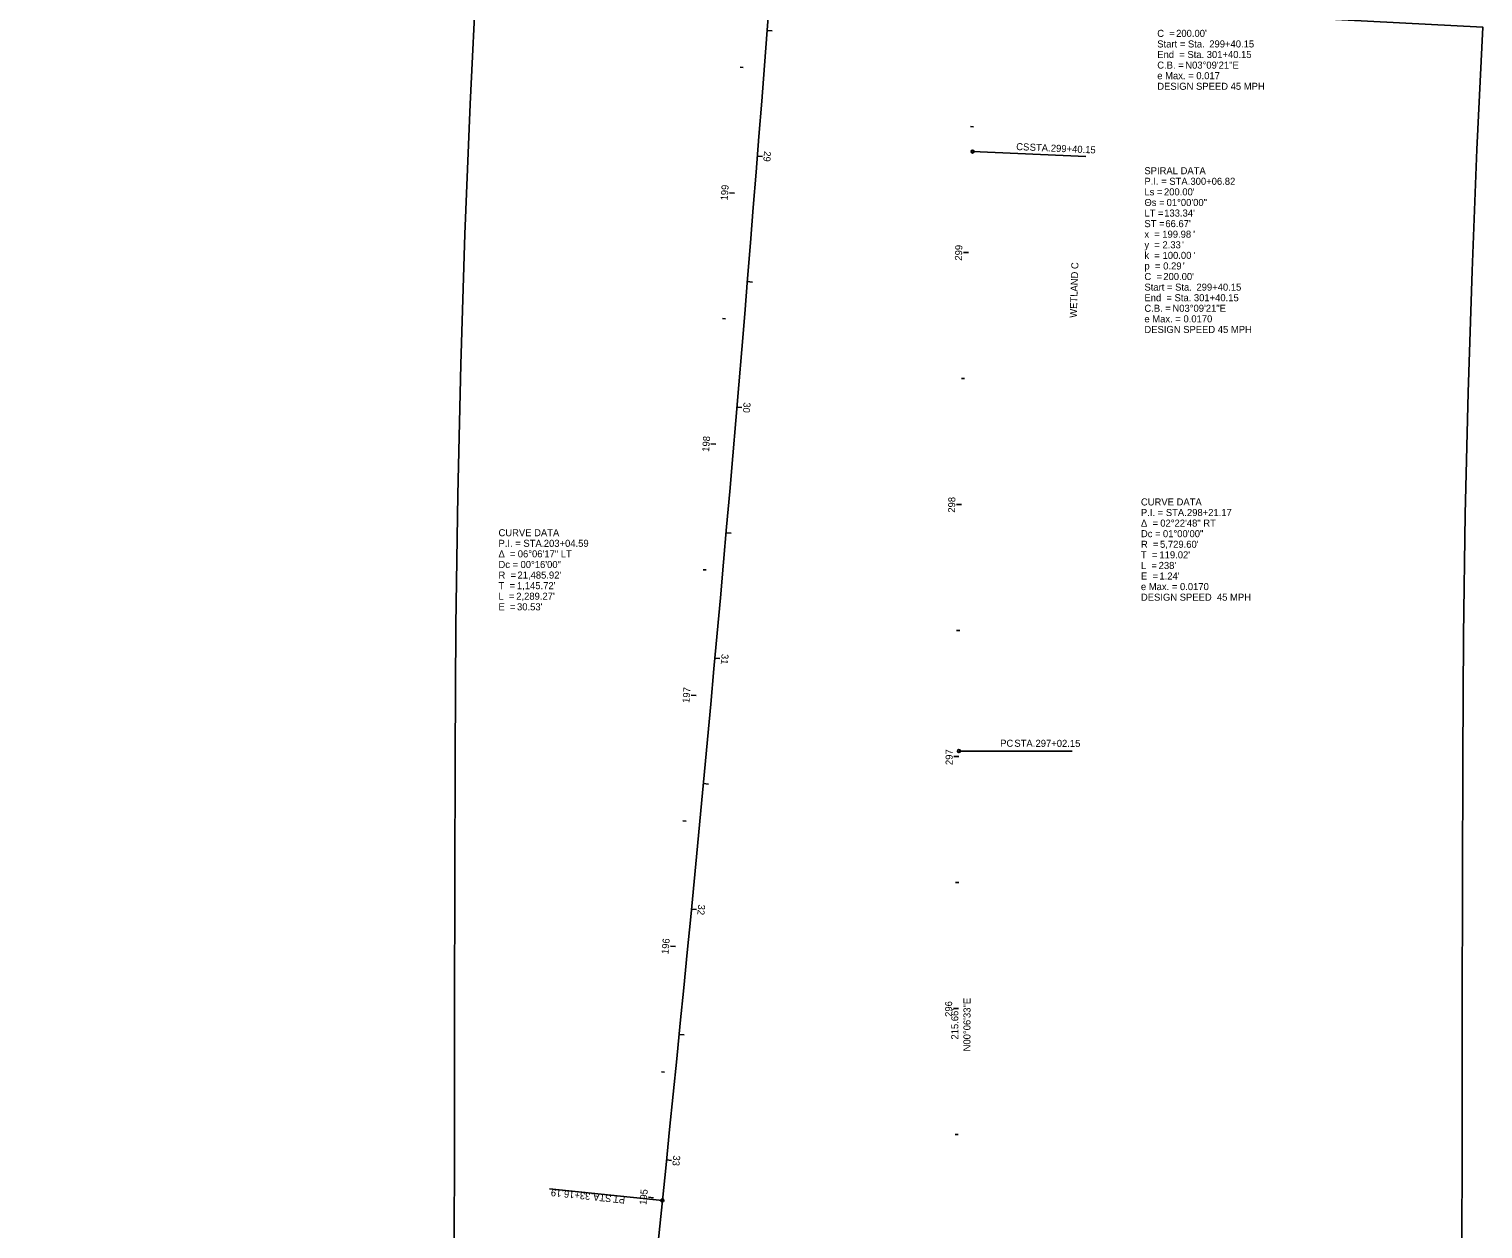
# Model space of a CAD drawing. Extents: x 172043 to 172958, y 249504 to 260295.
# Drawn here: x 172177 to 172754, y 256412 to 256888 of the extents above; entities that cross this region are included whole.
import ezdxf

# ---------------------------------------------------------------- set-up
doc = ezdxf.new("R2010")
doc.units = 0
for name, color, linetype in [('DR_X_Storm_Sewer', 7, 'Continuous'), ('LT_X_Poles', 7, 'Continuous'), ('PV_X_EOP', 7, 'Continuous'), ('RD_X_Fence', 7, 'Continuous'), ('RS_Raster1', 7, 'Continuous'), ('RW_X_CL_100_Bearings', 7, 'Continuous'), ('RW_X_CL_100_Cardinal_Points', 7, 'Continuous'), ('RW_X_CL_100_Curve_Data', 7, 'Continuous'), ('RW_X_CL_100_Stations', 7, 'Continuous'), ('SC_Scratch1', 7, 'Continuous')]:
    doc.layers.add(name, color=color, linetype=linetype)

msp = doc.modelspace()

# ---------------------------------------------------------------- linework, layer by layer
at = {"layer": 'DR_X_Storm_Sewer'}
msp.add_lwpolyline([(172345.99, 256399.91), (172745.99, 256399.15), (172746.09, 256449.15), (172746.18, 256499.15), (172746.28, 256549.15), (172746.37, 256599.15), (172746.66, 256647.48), (172747.36, 256695.73), (172748.49, 256743.97), (172750.04, 256792.2), (172752.01, 256840.45), (172754.37, 256888.9), (172354.92, 256909.87), (172352.41, 256858.44), (172350.3, 256806.77), (172348.64, 256755.05), (172347.43, 256703.32), (172346.68, 256651.58), (172346.37, 256599.91), (172346.28, 256549.91), (172346.18, 256499.91), (172346.09, 256449.91)], close=True, dxfattribs=at)
at = {"layer": 'PV_X_EOP'}
for p, q in [((172460.78, 256873), (172459.59, 256873.09)), ((172457.28, 256823.13), (172455.29, 256823.27)), ((172453.67, 256773.26), (172452.47, 256773.34)), ((172449.93, 256723.4), (172447.94, 256723.55)), ((172446.08, 256673.54), (172444.89, 256673.64)), ((172442.12, 256623.7), (172440.12, 256623.86)), ((172438.04, 256573.87), (172436.84, 256573.97)), ((172433.84, 256524.05), (172431.85, 256524.22)), ((172429.53, 256474.23), (172428.33, 256474.34)), ((172425.1, 256424.43), (172423.11, 256424.61))]:
    msp.add_line(p, q, dxfattribs=at)
at = {"layer": 'RW_X_CL_100_Bearings'}
for p, q in [((172551.77, 256839.6), (172596.73, 256837.65)), ((172546.38, 256601.68), (172591.38, 256601.6))]:
    msp.add_line(p, q, dxfattribs=at)
for centre in [(172551.77, 256839.6), (172546.38, 256601.68)]:
    msp.add_circle(centre, 0.6, dxfattribs=at)
at = {"layer": 'RW_X_CL_100_Stations'}
for p, q in [((172552.21, 256849.44), (172551.01, 256849.5)), ((172550.17, 256799.48), (172548.17, 256799.56)), ((172548.57, 256749.51), (172547.37, 256749.54)), ((172547.4, 256699.52), (172545.4, 256699.56)), ((172546.67, 256649.53), (172545.47, 256649.54)), ((172546.37, 256599.53), (172544.37, 256599.53)), ((172546.28, 256549.53), (172545.08, 256549.53)), ((172546.18, 256499.53), (172544.18, 256499.53)), ((172546.09, 256449.53), (172544.89, 256449.53))]:
    msp.add_line(p, q, dxfattribs=at)
at = {"layer": 'SC_Scratch1'}
for p, q in [((172470.23, 256887.67), (172472.22, 256887.52)), ((172466.38, 256837.82), (172468.37, 256837.66)), ((172466.38, 256837.82), (172468.37, 256837.66)), ((172462.38, 256787.98), (172464.38, 256787.81)), ((172458.24, 256738.15), (172460.24, 256737.98)), ((172458.24, 256738.15), (172460.24, 256737.98)), ((172453.96, 256688.33), (172455.95, 256688.16)), ((172449.52, 256638.53), (172451.51, 256638.35)), ((172449.52, 256638.53), (172451.51, 256638.35)), ((172444.94, 256588.74), (172446.93, 256588.55)), ((172440.22, 256538.96), (172442.21, 256538.77)), ((172440.22, 256538.96), (172442.21, 256538.77)), ((172435.34, 256489.2), (172437.33, 256489)), ((172430.32, 256439.45), (172432.31, 256439.25)), ((172430.32, 256439.45), (172432.31, 256439.25)), ((172428.67, 256423.35), (172383.9, 256427.98)), ((172428.67, 256423.35), (172177.28, 253990.91))]:
    msp.add_line(p, q, dxfattribs=at)
msp.add_circle((172428.67, 256423.35), 0.6, dxfattribs=at)
msp.add_arc((155518.73, 258170.95), 17000, 354.099581, 0.195474, dxfattribs=at)
msp.add_arc((155518.73, 258170.95), 17000, 354.099581, 0.195474, dxfattribs=at)

# ---------------------------------------------------------------- texts
at = {"layer": 'LT_X_Poles'}
msp.add_text('WETLAND C', height=2.8, rotation=88.23839, dxfattribs=at).set_placement((172593.15, 256773.59))
at = {"layer": 'PV_X_EOP'}
for s, rotation, p in [('199', 85.91824, (172454.56, 256820.09)), ('198', 85.65157, (172447.19, 256720.35)), ('197', 85.3849, (172439.37, 256620.67)), ('196', 85.11824, (172431.07, 256521.01)), ('195', 84.85157, (172422.32, 256421.46))]:
    msp.add_text(s, height=2.8, rotation=rotation, dxfattribs=at).set_placement(p)
at = {"layer": 'RD_X_Fence'}
for s, p in [('CURVE DATA', (172363.61, 256686.92)), ('P.I. = STA. ', (172363.61, 256682.72)), ('203+04.59', (172381.6, 256682.72)), ('Δ  = ', (172363.61, 256678.52)), ('06°06\'17" LT', (172371.26, 256678.52)), ('Dc = ', (172363.61, 256674.32)), ('00°16\'00"', (172372.36, 256674.32)), ('T  = ', (172363.61, 256665.92)), ('R  = ', (172363.61, 256670.12)), ("1,145.72'", (172370.93, 256665.92)), ("21,485.92'", (172371.15, 256670.12)), ('L  = ', (172363.61, 256661.72)), ("2,289.27'", (172370.65, 256661.72)), ('E  = ', (172363.61, 256657.52)), ("30.53'", (172370.96, 256657.52))]:
    msp.add_text(s, height=2.8, dxfattribs=at).set_placement(p)
at = {"layer": 'RS_Raster1'}
msp.add_text('N00°06\'33"E', height=2.8, rotation=89.89076, dxfattribs=at).set_placement((172550.95, 256482.48))
at = {"layer": 'RW_X_CL_100_Bearings'}
for s, rotation, p in [('CS', 357.51076, (172569.07, 256840.19)), (' STA. ', 357.51076, (172573.36, 256840)), ('299+40.15', 357.51076, (172582.81, 256839.59)), ('PC', 359.89076, (172562.74, 256603.38)), (' STA. ', 359.89076, (172567.33, 256603.37)), ('297+02.15', 359.89076, (172576.78, 256603.35))]:
    msp.add_text(s, height=2.8, rotation=rotation, dxfattribs=at).set_placement(p)
at = {"layer": 'RW_X_CL_100_Cardinal_Points'}
for s, p in [('C  = ', (172625.1, 256885.1)), ("200.00'", (172632.59, 256885.1)), ('Start = Sta. ', (172625.1, 256880.9)), ('299+40.15', (172645.75, 256880.9)), ('C.B. = ', (172625.1, 256872.5)), ('End  = Sta. ', (172625.1, 256876.7)), ('N03°09\'21"E', (172636.22, 256872.5)), ('301+40.15', (172644.73, 256876.7)), ('e Max. = 0.017', (172625.1, 256868.3)), ('DESIGN SPEED 45 MPH', (172625.1, 256864.1)), ('SPIRAL DATA', (172620, 256830.59)), ('P.I. = STA. ', (172620, 256826.39)), ('300+06.82', (172638.27, 256826.39)), ('Ls = ', (172620, 256822.19)), ("200.00'", (172627.76, 256822.19)), ('Θs = ', (172620, 256817.99)), ('01°00\'00"', (172628.81, 256817.99)), ('ST = ', (172620, 256809.59)), ('LT = ', (172620, 256813.79)), ("133.34'", (172627.86, 256813.79)), ("66.67'", (172628.31, 256809.59)), ('x  = ', (172620, 256805.39)), ('199.98', (172627.1, 256805.39)), ("'", (172639.39, 256805.39)), ('y  = ', (172620, 256801.19)), ('2.33', (172627.17, 256801.19)), ("'", (172634.98, 256801.19)), ('p  = ', (172620, 256792.79)), ('k  = ', (172620, 256796.99)), ('100.00', (172627.2, 256796.99)), ('0.29', (172627.46, 256792.79)), ("'", (172635.28, 256792.79)), ("'", (172639.49, 256796.99)), ('C  = ', (172620, 256788.59)), ("200.00'", (172627.5, 256788.59)), ('Start = Sta. ', (172620, 256784.39)), ('End  = Sta. ', (172620, 256780.19)), ('301+40.15', (172639.64, 256780.19)), ('299+40.15', (172640.66, 256784.39)), ('C.B. = ', (172620, 256775.99)), ('N03°09\'21"E', (172631.13, 256775.99)), ('e Max. = 0.0170', (172620, 256771.79)), ('DESIGN SPEED 45 MPH', (172620, 256767.59)), ('CURVE DATA', (172618.62, 256699.14)), ('P.I. = STA. ', (172618.62, 256694.94)), ('298+21.17', (172636.89, 256694.94)), ('Δ  = ', (172618.62, 256690.74)), ('02°22\'48" RT', (172626.3, 256690.74)), ('Dc = ', (172618.62, 256686.54)), ('R  = ', (172618.62, 256682.34)), ("5,729.60'", (172626.2, 256682.34)), ('01°00\'00"', (172627.36, 256686.54)), ('T  = ', (172618.62, 256678.14)), ("119.02'", (172625.96, 256678.14)), ('L  = ', (172618.62, 256673.94)), ("238'", (172625.66, 256673.94)), ('e Max. = 0.0170', (172618.62, 256665.54)), ('E  = ', (172618.62, 256669.74)), ("1.24'", (172625.96, 256669.74)), ('DESIGN SPEED  45 MPH', (172618.62, 256661.34))]:
    msp.add_text(s, height=2.8, dxfattribs=at).set_placement(p)
at = {"layer": 'RW_X_CL_100_Curve_Data'}
msp.add_text("215.66'", height=2.8, rotation=89.89076, dxfattribs=at).set_placement((172546.12, 256487.17))
at = {"layer": 'RW_X_CL_100_Stations'}
for s, rotation, p in [('299', 87.91228, (172547.55, 256796.26)), ('298', 88.91227, (172544.84, 256696.24)), ('297', 89.89076, (172543.87, 256596.12)), ('296', 89.89076, (172543.68, 256496.18))]:
    msp.add_text(s, height=2.8, rotation=rotation, dxfattribs=at).set_placement(p)
at = {"layer": 'SC_Scratch1'}
for s, rotation, p in [('29', 265.50227, (172469.04, 256839.82)), ('30', 265.16524, (172460.92, 256740.16)), ('31', 264.82821, (172452.2, 256640.33)), ('32', 264.49117, (172442.91, 256540.88)), ('33', 264.15414, (172433.03, 256441.34)), ('33+16.19', 174.09958, (172400.21, 256426.25)), (' STA. ', 174.09958, (172409.61, 256425.28)), ('PT', 174.09958, (172414, 256424.83))]:
    msp.add_text(s, height=2.8, rotation=rotation, dxfattribs=at).set_placement(p)

doc.saveas('drawing.dxf')
